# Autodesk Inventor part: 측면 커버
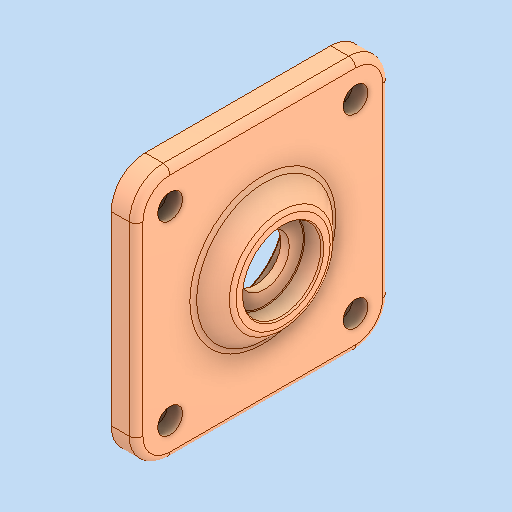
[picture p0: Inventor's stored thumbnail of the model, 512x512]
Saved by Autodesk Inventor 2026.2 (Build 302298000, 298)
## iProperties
Created: 2026-01
Part Number: 측면 커버
Material: 알루미늄 6061
Document SubType Name: Modeling
Designer: PC2-07
Density: 2.7 g/cm^3
Appearance: 기본값
Author: jhkim
Sending System: Autodesk Inventor 2026
Preprocessor: ST-DEVELOPER v20.1
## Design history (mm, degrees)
feature "솔리드1"
node "솔리드2"
